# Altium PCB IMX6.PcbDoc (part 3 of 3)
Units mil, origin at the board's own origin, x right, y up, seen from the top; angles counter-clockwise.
Board outline 7950 x 5550 mil, 4 copper layers (Top Layer, GND, VCC, Bottom Layer), stack 30.634 mil thick; 238 components, 319 nets, 1015 pads, 404 vias.
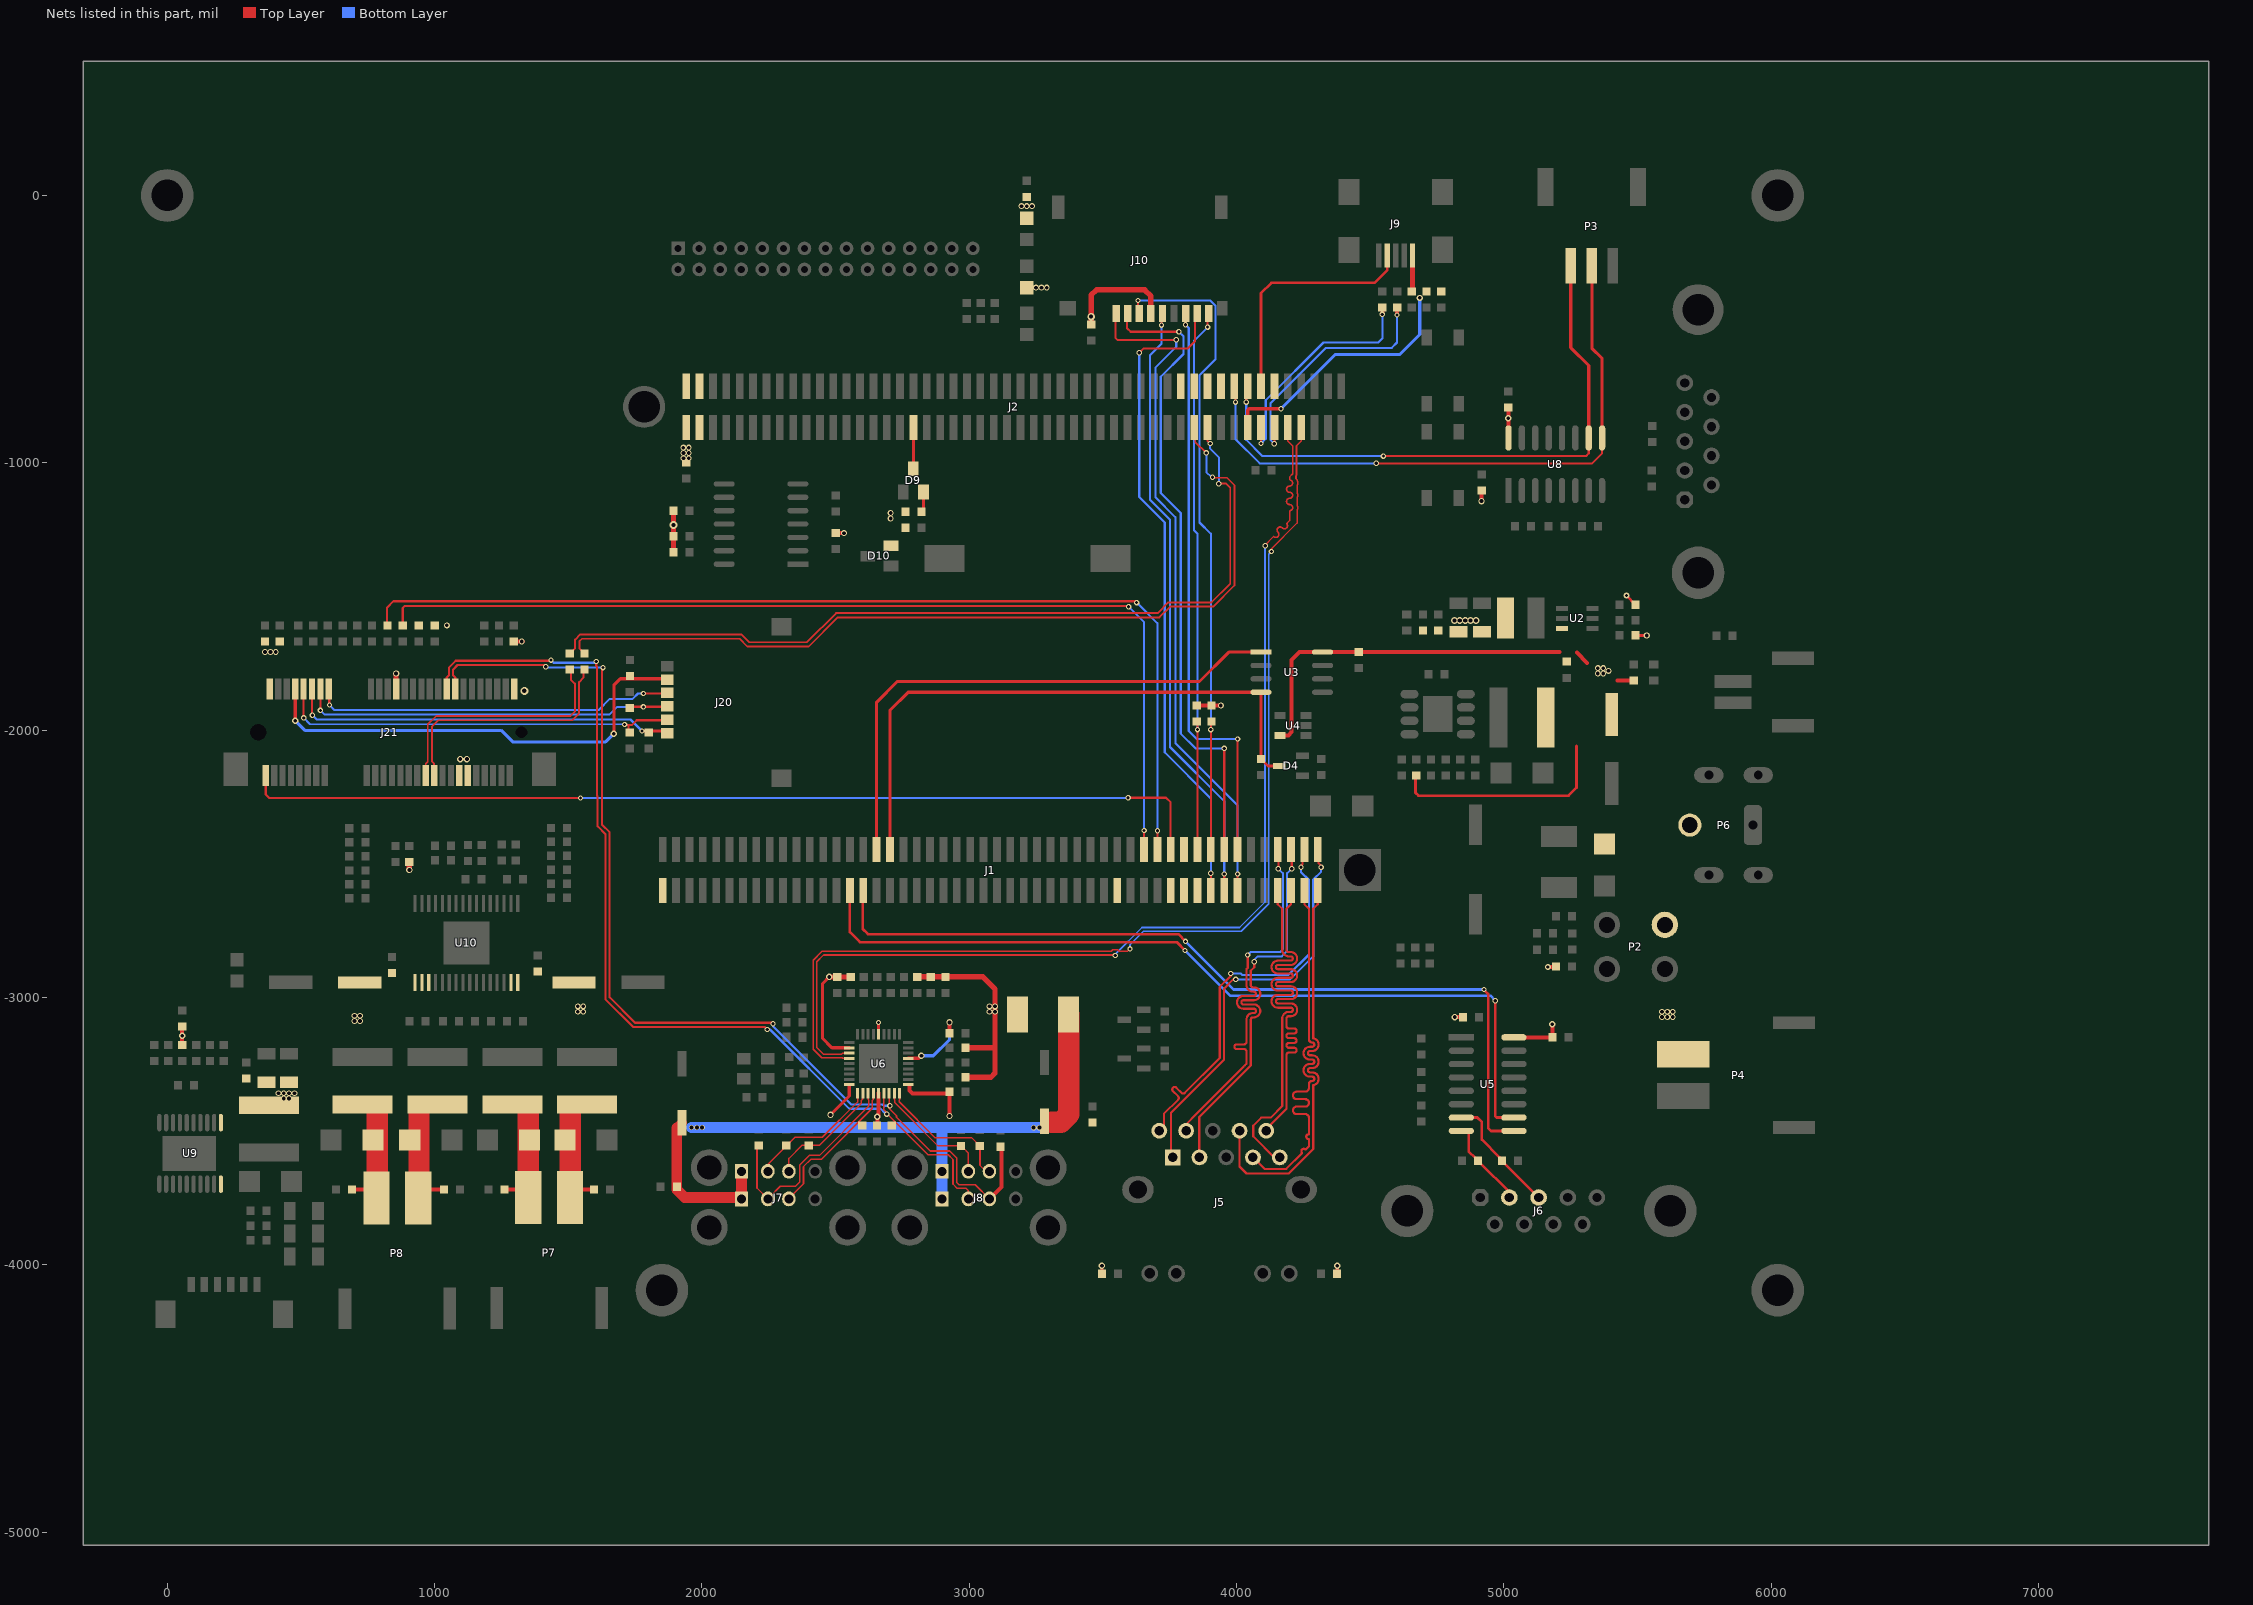
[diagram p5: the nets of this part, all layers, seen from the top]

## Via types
v1: diameter 20, hole 12, Top Layer to Bottom Layer, 138 vias
v2: diameter 22, hole 14, Top Layer to Bottom Layer, 54 vias
v3: diameter 24, hole 14, Top Layer to Bottom Layer, 53 vias
v4: diameter 22, hole 12, Top Layer to Bottom Layer, 39 vias
v5: diameter 23, hole 13, Top Layer to Bottom Layer, 38 vias
v6: diameter 22, hole 13, Top Layer to Bottom Layer, 21 vias
v7: diameter 30, hole 22, Top Layer to Bottom Layer, tented top, 15 vias
v8: diameter 22, hole 18, Top Layer to Bottom Layer, 6 vias
v9: diameter 25, hole 16, Top Layer to Bottom Layer, 5 vias
v10: diameter 24, hole 13, Top Layer to Bottom Layer, 5 vias
v11: diameter 20, hole 15, Top Layer to Bottom Layer, 5 vias
v12: diameter 30, hole 15, Top Layer to Bottom Layer, 4 vias
v13: diameter 18, hole 10, Top Layer to Bottom Layer, 4 vias
v14: diameter 20, hole 14, Top Layer to Bottom Layer, 4 vias
v15: diameter 28, hole 16, Top Layer to Bottom Layer, 3 vias
v16: diameter 26, hole 15, Top Layer to Bottom Layer, 3 vias
v17: diameter 45, hole 20, Top Layer to Bottom Layer, 1 vias
v18: diameter 28, hole 17, Top Layer to Bottom Layer, 1 vias
v19: diameter 25, hole 15, Top Layer to Bottom Layer, 1 vias
v20: diameter 28, hole 15, Top Layer to Bottom Layer, 1 vias
v21: diameter 18, hole 12, Top Layer to Bottom Layer, 1 vias
v22: diameter 30, hole 16, Top Layer to Bottom Layer, 1 vias
v23: diameter 25, hole 14, Top Layer to Bottom Layer, 1 vias

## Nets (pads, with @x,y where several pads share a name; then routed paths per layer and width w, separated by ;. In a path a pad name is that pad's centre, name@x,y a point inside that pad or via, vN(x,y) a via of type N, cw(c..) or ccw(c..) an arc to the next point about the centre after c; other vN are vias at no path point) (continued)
PCIE_TX_N: C118.1 J2.79 | length 3256.5
  Top Layer w7: C118.1@1506,-1713 1525.5,-1693.5 1525.5,-1661.37 1544.87,-1642 2147.63,-1642 2176.63,-1671 2393,-1671 2502,-1562 3704.37,-1562 3744.37,-1522 3906,-1522 3976,-1452 3976,-1093 3961,-1078 v1(3933,-1078) ; J2.79@3891.31,-867.49 3891.31,-918.73 3900.58,-928 v1(3901,-928)
  Bottom Layer w7: v1(3901,-928) 3901,-946.89 3933.84,-979.73 v1@3933.84,-1077
PCIE_TX_P: C119.1 J2.77 | length 3300.3
  Top Layer w7: C119.1@1561,-1713 1541.5,-1693.5 1541.5,-1668 1551.5,-1658 2141,-1658 2170,-1687 2399.63,-1687 2508.63,-1578 3711,-1578 3751,-1538 3912.63,-1538 3992,-1458.63 3992,-1084 3964,-1056 v1@3904,-1056 ; J2.77@3841.31,-867.49 3845.31,-871.49 3845.31,-922.31 v1(3886,-963)
  Bottom Layer w7: v1(3886,-963) 3887,-964 3887,-1035.31 v1@3904.69,-1053
  other v1: 3910,-1054
PCIE_TXO_N: C118.2 J21.31 | length 922.6
  Top Layer w7: J21.31@966.98,-2169.42 966.98,-2126.05 974.73,-2118.3 974.73,-1978.64 1006.37,-1947 1508.37,-1947 1524.69,-1930.69 1524.69,-1825.69 1510,-1811 C118.2@1510,-1778
PCIE_TXO_P: C119.2 J21.33 | length 919.2
  Top Layer w7: J21.33@998.48,-2169.42 998.48,-2126.05 990.73,-2118.3 990.73,-1985.27 1013,-1963 1515,-1963 1540.69,-1937.31 1540.69,-1820.31 1557,-1804 C119.2@1557,-1782
POR_B: D9.3 J2.35 | length 157.5
  Top Layer w12: J2.35@2791.31,-867.49 2791.31,-1018.31 D9.3@2796,-1023
PWM1_OUT: J1.1
RESET_B: D9.2 R93.1 | length 75.3
  Top Layer w12: R93.1@2826,-1183 2828.94,-1180.06 D9.2@2828.94,-1108.95
SATA_RX_N: J2.82
SATA_RX_P: J2.80
SATA_TX_N: J2.76
SATA_TX_P: J2.78
SD2_CD: J1.82 J10.9 R36.1 | length 2061.9
  Top Layer w8: J1.82@3853.52,-2446.23 v1(3853.52,-1998) R36.1@3853.52,-1970.52 ; v1(3891.5,-492.5) J10.9@3891.5,-437.89
  Bottom Layer w8: v1(3853.52,-1998) 3853.52,-1265.52 3841,-1253 3841,-543 v1(3891.5,-492.5)
SD2_CLK: J1.85 J10.5 | length 2295.4
  Top Layer w8: v1(3719,-485) J10.5@3719,-437.17 ; J1.85@3953.52,-2599.77 v1(3953.52,-2538)
  Bottom Layer w8: v1(3719,-485) 3719,-525 3719,-555 3676,-598 3676,-1138 3751,-1213 3751,-2063 3953.52,-2265.52 v1(3953.52,-2538)
SD2_CMD: J1.84 J10.3 R35.1 | length 2447
  Top Layer w8: J10.3@3629,-432.72 3631,-430.72 v1(3631,-393) ; J1.84@3903.52,-2446.23 v1(3903.52,-1998) R35.1@3903.52,-1965.52
  Bottom Layer w8: v1(3631,-393) 3901,-393 3921,-413 3921,-613 3861,-673 3861,-1223 3903.52,-1265.52 v1(3903.52,-1998)
SD2_DATA0: J1.88 J10.7 | length 2180.7
  Top Layer w8: J10.7@3806.14,-436.64 3809,-439.5 v1(3809,-484) ; J1.88@4003.52,-2446.23 v1(4003.52,-2033)
  Bottom Layer w8: v1(3809,-484) 3821,-496 3821,-2003 3851,-2033 v1(4003.52,-2033)
SD2_DATA1: J1.83 J10.8 | length 2438.4
  Top Layer w8: v1(3636,-588) 3651,-573 3816,-573 3844,-545 J10.8@3844,-455 ; J1.83@3903.52,-2599.77 v1(3903.52,-2535.52)
  Bottom Layer w8: v1(3636,-588) 3636,-1128 3731,-1223 3731,-2083 3903.52,-2255.52 v1(3903.52,-2535.52)
SD2_DATA2: J1.87 J10.1 | length 2546
  Top Layer w8: J10.1@3546.3,-436.64 3546.3,-532.3 3554,-540 v1(3774,-540) ; J1.87@4003.52,-2599.77 v1(4003.52,-2538)
  Bottom Layer w8: v1(3774,-540) 3774,-565.87 3696,-643.87 3696,-1128 3771,-1203 3771,-2048 4003.52,-2280.52 v1(4003.52,-2538)
SD2_DATA3: J1.86 J10.2 | length 2399.2
  Top Layer w8: J10.2@3589.61,-436.64 3589.61,-495.61 3604,-510 v1(3784,-510) ; J1.86@3953.52,-2446.23 v1(3953.52,-2068)
  Bottom Layer w8: v1(3784,-510) 3801,-527 3801,-593 3716,-678 3716,-1113 3791,-1188 3791,-2013 3846,-2068 v1(3953.52,-2068)
SD3_CMD: J1.77
SD3_DATA0: J1.80
SD3_DATA1: J1.74 R105.1 | length 3692.2
  Top Layer w8: R105.1@881,-1608 881,-1543 889,-1535 3593,-1535 v1@3600,-1542 ; J1.74@3654,-2415 v1@3654,-2374
  Bottom Layer w8: v1(3596,-1538) 3654,-1596 v1(3654,-2375)
SD3_DATA2: J1.76 R104.1 | length 3799.4
  Top Layer w8: R104.1@822,-1608 822,-1542 846,-1518 v1@3621,-1518 ; J1.76@3704,-2416 v1@3704,-2375
  Bottom Layer w8: v1@3627.5,-1523.5 3703.5,-1599.5 v1@3703.5,-2375.5
  other v1: 3704,-2376 3626,-1523
SD3_DATA4: J1.79
SD3_DATA5: J1.78 J21.1 | length 3616.8
  Top Layer w8: J21.1@368.56,-2182 368.56,-2240.56 381.56,-2253.56 v1(1546,-2253.56) ; J21.1@368.94,-2169.42 J21.1@369,-2163 ; v1(3594,-2253) 3736,-2253 3753,-2270 J1.78@3753,-2424
  Bottom Layer w8: v1(1546,-2253.56) v1@3595,-2253.56
SD3_DATA6: J1.81
SD3_DATA7: J1.69
SPEAK1+: C76.2 D14.K L9.2 P8.1 | length 402
  Top Layer w15: P8.1@974,-3718 C76.2@1036,-3718
  Top Layer w80: P8.1@941.91,-3748 L9.2@941.91,-3408
SPEAK1-: C80.1 D15.K L10.2 P8.2 | length 381
  Top Layer w15: C80.1@691,-3718 P8.2@762,-3718
  Top Layer w80: P8.2@786,-3718 L10.2@786,-3408
SPEAK2+: C70.2 D12.K L7.2 P7.1 | length 372
  Top Layer w15: P7.1@1534,-3718 C70.2@1596,-3718
  Top Layer w80: P7.1@1506.91,-3718 L7.2@1506.91,-3408
SPEAK2-: C72.1 D13.K L8.2 P7.2 | length 368
  Top Layer w15: C72.1@1261,-3718 P7.2@1324,-3718
  Top Layer w80: P7.2@1351,-3718 L8.2@1351,-3413
TRX0_N: J1.100 J5.2 | length 1505.7
  Top Layer w8: J5.2@3754,-3591 3754,-3431.63 3953,-3232.63 3953,-2966.81 3987.81,-2932 v1(3997,-2932) ; J1.100@4306.82,-2446.23 4306.82,-2497.52 4316,-2506.7 v1(4316,-2513)
  Bottom Layer w8: v1(3997,-2932) 4200.13,-2932 4286.5,-2845.63 4286.5,-2558.5 4316,-2529 v1(4316,-2513)
TRX0_P: J1.98 J5.1 | length 1456.8
  Top Layer w8: J5.1@3728,-3498 3728,-3435 3781,-3382 ccw(c3774.64,-3375.64) 3781,-3369.27 3761.82,-3350.09 cw(c3768.18,-3343.73) 3761.82,-3337.36 cw(c3768.18,-3343.73) 3774.55,-3337.36 3793.73,-3356.54 ccw(c3800.09,-3350.18) 3806.46,-3356.54 3937,-3226 3937,-2960.19 3978,-2919.19 v1(3978,-2910) ; v1(4241,-2513) 4241,-2507.68 4246.94,-2501.74 J1.98@4246.94,-2491.42
  Bottom Layer w8: v1(3978,-2910) 4015,-2910 4021,-2916 4193.5,-2916 4270.5,-2839 4270.5,-2560.5 4241,-2531 v1(4241,-2513) v1@4240.1,-2513.9
TRX1_N: J1.96 J5.4 | length 1506.9
  Top Layer w8: J5.4@3861,-3598 3860,-3597 3860,-3447 4053,-3254 4053,-3082 cw(c4061,-3082) 4061,-3074 4064.47,-3074 ccw(c4064.47,-3050) 4088.47,-3050 ccw(c4064.47,-3050) 4064.47,-3026 4025.53,-3026 cw(c4025.53,-3018) 4025.53,-3010 4064.47,-3010 ccw(c4064.47,-2986) 4088.47,-2986 ccw(c4064.47,-2986) 4064.47,-2962 4061,-2962 cw(c4061,-2954) 4053,-2954 4053,-2900 4066,-2887 v1(4066,-2866) ; J1.96@4203.52,-2446.23 4206,-2448.71 v1(4206,-2518)
  Bottom Layer w8: v1(4066,-2866) 4066,-2859 4079,-2846 4168.63,-2846 4189,-2825.63 4189,-2535 v1(4206,-2518)
TRX1_P: J1.94 J5.3 | length 1510
  Top Layer w8: J5.3@3811,-3498 3811,-3473.37 3848.69,-3435.69 4022.19,-3262.19 4030.64,-3253.74 4037,-3247.37 4037,-3202 ccw(c4028,-3202) 4028,-3193 4000.59,-3193 cw(c4000.59,-3184) 3991.59,-3184 cw(c4000.59,-3184) 4000.59,-3175 4028,-3175 ccw(c4028,-3166) 4037,-3166 4037,-3157 4037,-3148 4037,-3082 cw(c4061,-3082) 4061,-3058 4064.47,-3058 ccw(c4064.47,-3050) 4072.47,-3050 ccw(c4064.47,-3050) 4064.47,-3042 4025.53,-3042 cw(c4025.53,-3018) 4025.53,-2994 4064.47,-2994 ccw(c4064.47,-2986) 4072.47,-2986 ccw(c4064.47,-2986) 4064.47,-2978 4061,-2978 cw(c4061,-2954) 4037,-2954 4037,-2893.37 4041.69,-2888.69 4041.69,-2841.69 v1(4041,-2841) ; J1.94@4153.52,-2446.23 4156,-2448.71 v1(4156,-2518) v1@4154.05,-2518
  Bottom Layer w8: v1(4041,-2841) 4052,-2830 4162,-2830 4173,-2819 4173,-2535 v1(4156,-2518)
TRX2_N: J1.97 J5.8 | length 1572.1
  Top Layer w8: J5.8@4061,-3598 4104,-3641 4186,-3641 4244.66,-3582.34 ccw(c4243.95,-3581.64) 4244.66,-3580.93 cw(c4251.02,-3574.57) 4244.66,-3568.2 cw(c4251.02,-3574.57) 4257.38,-3568.2 ccw(c4258.09,-3567.49) 4258.8,-3568.2 4270.52,-3556.48 4270.52,-3530.48 ccw(c4269.52,-3530.48) 4269.52,-3529.48 cw(c4269.52,-3520.48) 4260.52,-3520.48 cw(c4269.52,-3520.48) 4269.52,-3511.48 ccw(c4269.52,-3510.48) 4270.52,-3510.48 4270.52,-3450 ccw(c4256.52,-3450) 4256.52,-3436 4224.52,-3436 cw(c4224.52,-3422) 4210.52,-3422 cw(c4224.52,-3422) 4224.52,-3408 4256.52,-3408 ccw(c4256.52,-3394) 4270.52,-3394 ccw(c4256.52,-3394) 4256.52,-3380 4224.52,-3380 cw(c4224.52,-3366) 4210.52,-3366 cw(c4224.52,-3366) 4224.52,-3352 4256.52,-3352 ccw(c4256.52,-3338) 4270.52,-3338 4270.52,-3324 cw(c4282.52,-3324) 4282.52,-3312 ccw(c4282.52,-3304) 4290.52,-3304 ccw(c4282.52,-3304) 4282.52,-3296 4274.52,-3296 cw(c4274.52,-3272) 4274.52,-3248 4282.52,-3248 ccw(c4282.52,-3240) 4290.52,-3240 ccw(c4282.52,-3240) 4282.52,-3232 4274.52,-3232 cw(c4274.52,-3208) 4274.52,-3184 4282.52,-3184 ccw(c4282.52,-3176) 4290.52,-3176 ccw(c4282.52,-3176) 4282.52,-3168 cw(c4282.52,-3156) 4270.52,-3156 4270.52,-2800.6 ; J1.97@4253.52,-2599.77 4253.52,-2651.02 4270.52,-2668.02 4270.52,-2804
TRX2_P: J1.99 J5.7 | length 1554.4
  Top Layer w8: J5.7@4011,-3504 4011,-3632 4037,-3658 4195,-3658 4286.52,-3566.48 4286.52,-3327.66 ccw(c4282.52,-3304) 4306.52,-3304 ccw(c4282.52,-3304) 4282.52,-3280 4274.52,-3280 cw(c4274.52,-3272) 4274.52,-3264 4282.52,-3264 ccw(c4282.52,-3240) 4306.52,-3240 ccw(c4282.52,-3240) 4282.52,-3216 4274.52,-3216 cw(c4274.52,-3208) 4274.52,-3200 4282.52,-3200 ccw(c4282.52,-3176) 4306.52,-3176 ccw(c4282.52,-3176) 4286.52,-3152.34 4286.52,-2800.6 ; 4286.52,-2804 4286.52,-2668.02 4303.52,-2651.02 J1.99@4303.52,-2599.77
TRX3_N: J1.93 J5.10 | length 1563.9
  Top Layer w8: J5.10@4147,-3600 4143,-3600 4062,-3519 4062,-3479 4092,-3449 4127,-3449 4170.52,-3405.48 4170.52,-3078 cw(c4194.52,-3078) 4194.52,-3054 4202.41,-3054 ccw(c4202.41,-3046) 4210.41,-3046 ccw(c4202.41,-3046) 4202.41,-3038 4154.63,-3038 cw(c4154.63,-3014) 4154.63,-2990 4202.41,-2990 ccw(c4202.41,-2982) 4210.41,-2982 ccw(c4202.41,-2982) 4202.41,-2974 4154.63,-2974 cw(c4154.63,-2950) 4154.63,-2926 4202.41,-2926 ccw(c4202.41,-2918) 4210.41,-2918 ccw(c4202.41,-2918) 4202.41,-2910 4154.63,-2910 cw(c4154.63,-2886) 4154.63,-2862 4202.41,-2862 ccw(c4202.41,-2854) 4210.41,-2854 ccw(c4202.41,-2854) 4202.41,-2846 4194.52,-2846 cw(c4194.52,-2822) 4170.52,-2822 4170.52,-2668.02 4153.52,-2651.02 J1.93@4153.52,-2599.77
  Bottom Layer w8: J5.10@4161,-3598 J5.10@4166,-3598
TRX3_P: J1.95 J5.9 | length 1564.3
  Top Layer w8: J5.9@4108,-3494 4186.52,-3415.48 4186.52,-3276 4186.52,-3215 cw(c4195.52,-3215) 4195.52,-3206 4215.32,-3206 ccw(c4215.32,-3197) 4224.32,-3197 ccw(c4215.32,-3197) 4215.32,-3188 4195.52,-3188 cw(c4195.52,-3179) 4186.52,-3179 cw(c4195.52,-3179) 4195.52,-3170 4215.32,-3170 ccw(c4215.32,-3161) 4224.32,-3161 ccw(c4215.32,-3161) 4215.32,-3152 4195.52,-3152 cw(c4195.52,-3143) 4186.52,-3143 cw(c4195.52,-3143) 4195.52,-3134 4215.32,-3134 ccw(c4215.32,-3125) 4224.32,-3125 ccw(c4215.32,-3125) 4215.32,-3116 4195.52,-3116 cw(c4195.52,-3107) 4186.52,-3107 4186.52,-3078 cw(c4194.52,-3078) 4194.52,-3070 4202.41,-3070 ccw(c4202.41,-3046) 4226.41,-3046 ccw(c4202.41,-3046) 4202.41,-3022 4154.63,-3022 cw(c4154.63,-3014) 4154.63,-3006 4202.41,-3006 ccw(c4202.41,-2982) 4226.41,-2982 ccw(c4202.41,-2982) 4202.41,-2958 4154.63,-2958 cw(c4154.63,-2950) 4154.63,-2942 4202.41,-2942 ccw(c4202.41,-2918) 4226.41,-2918 ccw(c4202.41,-2918) 4202.41,-2894 4154.63,-2894 cw(c4154.63,-2886) 4154.63,-2878 4202.41,-2878 ccw(c4202.41,-2854) 4226.41,-2854 ccw(c4202.41,-2854) 4202.41,-2830 4194.52,-2830 cw(c4194.52,-2822) 4186.52,-2822 4186.52,-2668.02 4203.52,-2651.02 J1.95@4203.52,-2599.77
  Bottom Layer w8: J5.9@4111,-3499.47 J5.9@4111,-3498
U2_RXD: D20.1 J6.2 U5.8 | length 290.2
  Top Layer w10: U5.8@4861,-3498 4868,-3505 4868,-3575 D20.1@4893,-3600 ; D20.1@4910.5,-3618.5 5020.17,-3728.17 J6.2@5020.17,-3748
U2_TXD: D21.1 J6.3 U5.7 | length 388.7
  Top Layer w10: U5.7@4875.24,-3448.91 4899.91,-3448.91 4917,-3466 4917,-3531 D21.1@4984,-3598 ; D21.1@5002,-3620.67 J6.3@5129.33,-3748
UART1_RX: J2.84 P3.2 U8.9 | length 2336.2
  Top Layer w8: J2.84@3991.31,-713.94 3996,-718.63 v1(3996,-773) ; v1(4522,-1002) 5329.61,-1002 5366.91,-964.7 U8.9@5366.91,-906.91
  Top Layer w12: P3.2@5328.74,-263 5328.74,-571.74 5366.91,-609.91 U8.9@5366.91,-906.91
  Bottom Layer w8: v1@3996,-778 3996,-912 4086,-1002 v1(4522,-1002)
UART1_TX: J2.86 P3.1 U8.10 | length 2237.1
  Top Layer w8: v1(4036,-773) 4036,-719.26 J2.86@4041.31,-713.94 ; v1(4549,-975) 5306.61,-975 5316.91,-964.7 U8.10@5316.91,-906.91
  Top Layer w12: P3.1@5250,-263 5250,-569 5316.91,-635.91 U8.10@5316.91,-906.91
  Bottom Layer w8: v1@4036,-778 4036,-914 4097,-975 v1(4549,-975)
UART2_RX: J1.31 U5.9 | length 3178.3
  Top Layer w10: J1.31@2601.52,-2599.77 2601.52,-2743.52 2621,-2763 3782,-2763 v1(3809,-2790) ; v1@4925,-2971 4941,-2987 4941,-3488 4951.91,-3498.91 U5.9@5037.09,-3498.91
  Bottom Layer w10: v1(3809,-2790) 3989,-2970 v1@4918,-2970
  other v1: 4925,-2970
UART2_TX: J1.29 U5.10 | length 3178.5
  Top Layer w10: J1.29@2553.52,-2599.48 2553.52,-2755.52 2591,-2793 3776,-2793 v1(3807,-2824) ; v1@4966.91,-3013 4966.91,-3443.91 4971.91,-3448.91 U5.10@5037.09,-3448.91
  Bottom Layer w10: v1(3807,-2824) 3976,-2993 4949,-2993 v1@4967,-3011
  other v1: 4967,-3012
UART3_RX: J1.34 U3.1 | length 2055.9
  Top Layer w12: J1.34@2653.52,-2446.23 2653.52,-1895.48 2731,-1818 3861,-1818 3971,-1708 U3.1@4081,-1708
UART3_TX: D4.3 J1.36 R18.2 U3.4 | length 2265.9
  Top Layer w10: U3.4@4091,-1858 R18.2@4091,-2108 4117.06,-2134.06 D4.3@4159.95,-2134.06
  Top Layer w12: J1.36@2703.52,-2446.23 2703.52,-1925.48 2771,-1858 U3.4@4091,-1858
UIM_CLK: D31.1 J20.6 J21.12 | length 1469
  Top Layer w8: v1@542,-1946 J21.12@542,-1831.36 ; J20.6@1865.44,-2003 J20.6@1870.44,-2008
  Top Layer w10: v1(1776,-2003) J20.6@1865.44,-2003
  Bottom Layer w8: v1@543,-1943 560,-1960 1733,-1960 v1(1776,-2003)
  other v1: 543,-1944
UIM_DATA: D30.2 J20.5 J21.10 | length 1496.7
  Top Layer w8: v1@510,-1957 J21.10@510,-1861.36 ; J21.10@510.02,-1846.58 J21.10@510,-1843 ; v1@1711.17,-1980.17 1738.83,-1980.17 1756,-1963 J20.5@1864,-1963 ; D30.2@1725.09,-2007.91 1725.09,-1981.08
  Bottom Layer w8: v1(511,-1954) 534.25,-1977.29 v1@1712,-1978.37
  other v1: 1711,-1979
UIM_PWR: C1.1 J20.2 J21.8 | length 1753.1
  Top Layer w8: J21.8@477,-1840 J21.8@477.23,-1846.64
  Top Layer w12: v10@479,-1966 J21.8@479,-1842 ; v10@1671,-2005 1671,-1832 1695,-1808 J20.2@1870.44,-1808
  Bottom Layer w12: v10(479,-1965) 515,-2001 1249,-2001 1292,-2044 1639.72,-2044 v10@1672.72,-2011
  other v10: 1671,-2013
UIM_RESET: D32.1 J20.4 J21.14 | length 1470.2
  Top Layer w8: v1@573,-1928 J21.14@573,-1824.36
  Top Layer w10: D32.1@1730.09,-1913 J20.4@1874,-1913
  Bottom Layer w8: v1(573,-1926) 589,-1942 1654,-1942 1683,-1913 v1@1777,-1913
  other v1: 1781,-1913
UIM_VPP: J20.3 J21.16 | length 1356.8
  Top Layer w8: v1@606,-1906 J21.16@606,-1825.36 ; v1(1781,-1863) J20.3@1860,-1863
  Bottom Layer w8: v1@608,-1907 626,-1925 1613,-1925 1655,-1883 1741,-1883 1761,-1863 v1@1772,-1863
  other v1: 607,-1906
USB_H1_D_N: J2.91 U6.30 | length 4163.3
  Top Layer w6: U6.30@2550.76,-3207.72 2527.08,-3207.72 2523.24,-3211.57 2454.37,-3211.57 2430,-3187.2 2430,-2866.17 2455.17,-2841 3536.69,-2841 3540.34,-2837.34 v1(3546,-2843) ; v1(4107,-1310) 4107,-1309 4106,-1308 4138.21,-1275.79 ccw(c4146.34,-1267.66) 4154.47,-1259.53 cw(c4162.6,-1251.4) 4170.74,-1243.26 ccw(c4178.87,-1235.13) 4187,-1227 4198,-1216 4198,-1179 ccw(c4198,-1167.5) 4198,-1156 cw(c4198,-1144.5) 4198,-1133 ccw(c4198,-1121.5) 4198,-1110 cw(c4198,-1098.5) 4198,-1087 ccw(c4198,-1075.5) 4198,-1064 4198,-1053 4210,-1041 4210,-937.42 4191.31,-918.73 J2.91@4191.31,-867.49
  Bottom Layer w6: v1(3546,-2843) 3546,-2838 3646,-2738 4011,-2738 4106,-2643 v1@4106,-1308
USB_H1_D_P: J2.93 U6.31 | length 4127.2
  Top Layer w6: U6.31@2550.76,-3227.41 2527.08,-3227.41 2525.24,-3225.57 2448.57,-3225.57 2416,-3193 2416,-2860.37 2449.37,-2827 3530.89,-2827 3536.89,-2821 3555.11,-2821 3561.11,-2827 3592,-2827 v1(3601,-2818) ; v1(4130,-1332) 4130,-1321 4226,-1225 4226,-1179.19 4226.31,-1178.88 4226.31,-1178.35 4226.86,-1177.8 4226.86,-1175.97 4227.29,-1175.54 4227.29,-1174.83 4227.41,-1174.7 4227.41,-1173.56 4227.85,-1173.13 4227.85,-1170.21 4228.08,-1169.98 4228.08,-1165.02 4227.85,-1164.79 4227.85,-1161.87 4227.41,-1161.44 4227.41,-1160.3 4227.29,-1160.17 4227.29,-1159.46 4226.86,-1159.03 4226.86,-1157.2 4226.31,-1156.65 4226.31,-1156.12 4226,-1155.81 4226,-1133.19 4226.31,-1132.88 4226.31,-1132.35 4226.86,-1131.8 4226.86,-1129.97 4227.29,-1129.54 4227.29,-1128.83 4227.41,-1128.7 4227.41,-1127.56 4227.85,-1127.13 4227.85,-1124.21 4228.08,-1123.98 4228.08,-1119.02 4227.85,-1118.79 4227.85,-1115.87 4227.41,-1115.44 4227.41,-1114.3 4227.29,-1114.17 4227.29,-1113.46 4226.86,-1113.03 4226.86,-1111.2 4226.31,-1110.65 4226.31,-1110.12 4226,-1109.81 4226,-1087.19 4226.31,-1086.88 4226.31,-1086.35 4226.86,-1085.8 4226.86,-1083.97 4227.29,-1083.54 4227.29,-1082.83 4227.41,-1082.7 4227.41,-1081.56 4227.85,-1081.13 4227.85,-1078.21 4228.08,-1077.98 4228.08,-1073.02 4227.85,-1072.79 4227.85,-1069.87 4227.41,-1069.44 4227.41,-1068.3 4227.29,-1068.17 4227.29,-1067.46 4226.86,-1067.03 4226.86,-1065.2 4226.31,-1064.65 4226.31,-1064.12 4222,-1059.81 4222,-1048.8 4224,-1046.8 4224,-936.05 4241.31,-918.73 J2.93@4241.31,-867.49
  Bottom Layer w6: v1(3601,-2818) 3601,-2802.8 3651.8,-2752 4016.8,-2752 4120,-2648.8 4120,-1342 v1(4130,-1332)
USB_H1_OC: J2.90
USB_OTG_D_N: J2.89 R33.2 | length 905.7
  Top Layer w8: v1(4141,-928.51) J2.89@4141,-878
  Top Layer w15: v1(4600,-447) R33.2@4600,-420
  Bottom Layer w8: v1(4141,-928.51) 4126,-913.51 4126,-778 4334,-570 4580,-570 4600,-550 v1(4600,-447)
USB_OTG_D_P: J2.87 R34.2 | length 866.7
  Top Layer w8: v1@4091,-928.51 J2.87@4091,-878
  Top Layer w15: v1(4545,-445) R34.2@4545,-420
  Bottom Layer w8: v1(4091,-928) 4109,-910 4109,-766 4325,-550 4530,-550 4545,-535 v1(4545,-445)
USB_OTG_ID: J2.88 J9.4 | length 910.6
  Top Layer w10: J2.88@4091.31,-713.94 4091.31,-365.69 4130,-327 4516,-327 4563.5,-279.5 J9.4@4563.5,-225
USB_OTG_VBUS: C47.2 C48.2 C49.2 J2.85 J9.1 | length 1094.6
  Top Layer w12: J2.85@4041.31,-867.49 4041.31,-802.69 4046,-798 v1(4166,-798)
  Top Layer w18: C48.2@4658,-354.01 J9.1@4658,-222
  Bottom Layer w12: v1(4166,-798) 4369,-595 4610,-595 4685,-520 v5(4685,-383)
USB_PORT1_N: D22.1 J7.2 U6.1 | length 491.4
  Top Layer w6: J7.2@2246.63,-3649.97 2246.63,-3624.37 2348,-3523 2450,-3523 2582.26,-3390.74 U6.1@2582.26,-3357.33
USB_PORT1_P: D24.1 J7.3 U6.2 | length 446
  Top Layer w6: J7.3@2325.37,-3649.97 2325.37,-3601.63 2374,-3553 2439.8,-3553 2596.26,-3396.54 2596.26,-3384.74 2601.95,-3379.06 U6.2@2601.95,-3357.33 U6.2@2601.77,-3357.5
USB_PORT2_N: D23.2 J7.6 U6.3 | length 815.5
  Top Layer w6: D23.2@2211.91,-3553.09 2206,-3559 2206,-3712.49 J7.6@2246.63,-3753.12 ; J7.6@2254.5,-3744.5 2293,-3706 2350,-3706 2366,-3690 2366,-3626.37 2401.96,-3590.41 2439.59,-3590.41 2623.47,-3406.53 2623.47,-3382.86 2621.63,-3381.02 U6.3@2621.63,-3357.33
USB_PORT2_P: D25.2 J7.7 U6.4 | length 566.5
  Top Layer w6: J7.7@2313.81,-3764.81 2313.81,-3762.19 2375,-3701 2375,-3700.8 2380,-3695.8 2380,-3632.17 2407.76,-3604.41 2447.59,-3604.41 2637.47,-3414.53 2637.47,-3384.86 2641.32,-3381.02 U6.4@2641.32,-3357.33
USB_PORT3_N: D27.2 J8.6 J21.36 U6.6 | length 3774.5
  Top Layer w6: U6.6@2680.68,-3357.33 2680.68,-3419.68 2691,-3430 v1(2691,-3436) v1@2697,-3436 ; v1@2693.5,-3435.5 2846,-3588 2921,-3588 2939,-3606 2939,-3697.63 2955.37,-3714 2989,-3714 2996.63,-3721.63 J8.6@2996.63,-3753.12
  Top Layer w8: J21.36@1045.73,-1846.58 1045.73,-1803.21 1053.47,-1795.46 1053.47,-1766.37 1079.36,-1740.49 v1@1435.49,-1740.49 ; v1@1435.49,-1743 v1(1435.49,-1738) ; v1(1605,-1743) 1605,-1759.37 1608,-1762.37 1608,-2246 1610,-2248 1610,-2359.63 1638.81,-2388.44 1638.81,-3005.81 1743.19,-3110.19 2235.56,-3110.19 v1(2244.69,-3119.31) ; D27.2@2700.09,-3477.91 D27.2@2708,-3470.01
  Bottom Layer w8: v1(1435.49,-1738) 1445.49,-1748 v1@1604,-1748 ; v1(2244.69,-3119.31) 2254.69,-3119.31 2551.37,-3416 2668.37,-3416 2684.37,-3432 v1@2694,-3432 ; v1(2691,-3436) 2692,-3436 v1@2695,-3433
USB_PORT3_P: D29.2 J8.7 J21.38 U6.7 | length 3947.7
  Top Layer w6: U6.7@2700.37,-3357.33 2700.37,-3415.09 2718.24,-3433 2727.68,-3442.44 2727.68,-3447.68 2854,-3574 2926.8,-3574 2953,-3600.2 2953,-3691.83 2961.17,-3700 3022.25,-3700 J8.7@3075.37,-3753.12
  Top Layer w8: J21.38@1077.22,-1846.58 1077.22,-1803.21 1069.47,-1795.46 1069.47,-1773 1085.98,-1756.49 1411.49,-1756.49 1416,-1761 v1(1416,-1763) ; v1(1630,-1766) 1626,-1770 1626,-2353 1654.81,-2381.81 1654.81,-2999.19 1749.81,-3094.19 2263.19,-3094.19 v1@2266.5,-3097.5 ; v1(2266,-3098) v1@2267,-3098 ; J8.7@3075.37,-3753.12 J8.7@3075.88,-3753.12
  Top Layer w15: J8.7@3075.88,-3753.12 3121,-3708 D29.2@3121,-3568
  Bottom Layer w8: v1@1422,-1766 v1(1630,-1766) ; v1(2266,-3098) 2266,-3108 2558,-3400 2675,-3400 2682,-3407 2684,-3405 v1(2703,-3405)
USB_PORT4_N: D26.1 J8.2 U6.8 | length 441.9
  Top Layer w6: U6.8@2720.05,-3357.33 2720.05,-3381.02 2721.9,-3382.86 2721.9,-3393.63 2883.27,-3555 D26.1@2968,-3555 ; D26.1@2980,-3565 2996.63,-3581.63 J8.2@2996.63,-3649.97
USB_PORT4_P: D28.1 J8.3 U6.9 | length 515.3
  Top Layer w6: U6.9@2739.74,-3357.33 2739.74,-3381.02 2737.9,-3382.86 2737.9,-3389.83 2873.07,-3525 3010,-3525 3040,-3555 3040,-3628 3063,-3651 J8.3@3069,-3651
VBUS: C29.1 C30.2 C36.1 C37.2 F2.2 J7.1 J7.5 J8.1 J8.5 | length 2626.3
  Top Layer w35: 1906,-3488 C36.1@1926,-3468
  Top Layer w40: 1906,-3488 1906,-3718 1936,-3748 2143.09,-3748 J7.5@2148.2,-3753.12 J7.1@2148.2,-3649.97
  Top Layer w80: 3308,-3466 3343,-3466 3371.94,-3437.06 F2.2@3371.94,-3063
  Bottom Layer w30: J8.5@2898,-3756 J8.5@2898.02,-3753.12
  Bottom Layer w40: v11(1961,-3486) v11(1981,-3486) v11(2001,-3486) v11@3261,-3486 ; J8.5@2898.2,-3747 2898.2,-3491.8
  other v11: 3241,-3487 3262,-3487
VCC3V3: C7.2 C25.2 C32.2 C34.2 C35.2 C40.2 C41.2 C42.2 C43.2 C44.2 C50.2 C86.1 C87.1 C88.1 C109.1 C110.1 C111.1 D10.2 J10.4 J21.2 J21.24 J21.39 J21.41 J21.52 L5.2 L11.1 R9.2 R10.2 R11.2 R19.2 R24.1 R35.2 R36.2 R44.2 R57.1 R58.1 R89.1 R90.1 R93.2 R112.2 R113.2 R114.2 R115.2 U5.16 U6.5 U6.10 U6.15 U6.23 U6.29 U6.36 U8.16 | length 2654.1
  Top Layer w12: v3(2476,-2923) 2451,-2948 2451,-3153 2486.04,-3188.04 U6.29@2550.76,-3188.04 ; v3(2481,-3439) 2481,-3438 2550.76,-3368.24 U6.36@2550.76,-3325.83 ; U6.23@2661,-3136.86 v21(2661,-3093) ; U6.15@2771.24,-3227.41 2811.59,-3227.41 v3(2821,-3218) ; R10.2@3496,-4033 v3(3496,-4003) ; R11.2@4376,-4033 v3(4376,-4003) ; R58.1@5490,-1646 v3(5534,-1646)
  Top Layer w15: R44.2@56,-3178 C32.2@56,-3108 ; C43.2@1296,-1668 v2@1331,-1668 ; R112.2@2501,-1263 v2(2531,-1263) ; C41.2@2651,-3478 2656,-3473 v3(2656,-3446) 2661,-3441 U6.5@2661,-3357.33 ; 2776,-3333 2776,-3348 2787.38,-3359.38 2919.62,-3359.38 C42.2@2926,-3353 v3(2926,-3443) ; C109.1@2926,-3133 v3(2926,-3093) ; R36.2@3856,-1908 v2(3941,-1908) ; v3(4816,-3073) C25.2@4846,-3073 ; v3(4916,-1143) C7.2@4916,-1103 ; U8.16@5016.91,-906.91 C35.2@5016.91,-793.91 ; U5.16@5037.09,-3148.91 C34.2@5180.09,-3148.91 ; v3(5180,-3100) 5181,-3101 C34.2@5181,-3148
  Top Layer w20: v3(856,-1788) 856,-1845.83 J21.24@856.75,-1846.58 ; v3(906,-2523) R57.1@906,-2493 ; R113.2@1894,-1333 R115.2@1894,-1179 ; v3(2476,-2923) R19.2@2506,-2923 R24.1@2556,-2923 ; C110.1@3456,-483 3456,-373 3476,-353 3656,-353 3679.22,-376.22 J10.4@3679.22,-441.64
  Bottom Layer w12: v3(2821,-3218) 2866.04,-3218 2926,-3158.04 v3(2926,-3093)
  other v2: 366,-1708 386,-1708 406,-1708 1326,-1668 1046,-1608 2706,-1208 2706,-1188 3195,-40 3215,-40 3235,-40
  other v3: 56,-3143 1096,-2108 1121,-2108 5016,-833
  other v9: 4815,-1590 4835,-1590 4855,-1590 4875,-1590 4895,-1590
  other v12: 1894,-1233
  other v20: 3456,-453
  other v22: 1336,-1853
VCC5V: C2.1 C5.1 C17.1 C18.1 C23.1 F2.1 J2.1 J2.2 J2.3 J2.4 L1.2 L4.1 R2.2 R3.1 R4.1 R17.1 R20.1 R21.1 R22.1 R23.1 U2.3 U3.8 U4.5 | length 3191.8
  Top Layer w10: R2.2@4669,-2170 4669,-2234 4680,-2245 5241,-2245 5271,-2215 5271,-2059 ; v4@5457.5,-1496.5 R4.1@5492,-1531
  Top Layer w15: 3095.96,-3188.04 3096,-3188 ; U4.5@4162.77,-2020.4 4193.28,-2020.4 4206,-2007.69 4206,-1738 4236,-1708 U3.8@4321.31,-1708 5207,-1708 ; v4(5164,-2886) R17.1@5188,-2886 ; 5273,-1710 5311,-1748 ; 5425,-1815 R3.1@5485,-1815
  Top Layer w20: R23.1@2806.04,-2922.68 3050.68,-2922.68 3096,-2968 3096,-3188 3096,-3283 3080.96,-3298.04 R20.1@2986,-3298 ; 3001.32,-3188.04 3095.96,-3188.04
  other v2: 3076,-3053 3096,-3053 3076,-3033 3096,-3033 5351,-1788 5371,-1788 5391,-1778 5351,-1768 5371,-1768 1931,-983 1951,-983 1931,-963 1951,-963 3250,-345 3270,-345 3290,-345
  other v4: 5458,-1496
  other v6: 1931,-943 1951,-943
VIN: C57.1 C58.2 C59.2 C65.1 C66.1 C83.1 C84.1 D2.A L6.1 P2.4 P4.1 P6.2 U9.1 U9.20 U10.17 U10.18 U10.19 U10.31 U10.32
  other v2: 436,-3378 456,-3378 416,-3358 436,-3358 456,-3358 476,-3358 701,-3088 721,-3088 5591,-3073 5611,-3073 5631,-3073 701,-3068 721,-3068 1536,-3053 1556,-3053 5591,-3053 5611,-3053 5631,-3053 1536,-3033 1556,-3033
pads on no net: D4.2 D9.1 J3.1 J3.4 J3.6 J3.7 J3.8 J3.9 J6.1 J6.4 J6.6 J6.7 J6.8 J6.9 J20. J21.3 J21.5 J21.7 J21.17 J21.19 J21.42 J21.44 J21.45 J21.46 J21.47 J21.49 J21.51 J21.53 J21.54 J21.55 J21.56 U1.3 U4.1 U5.11 U5.12 U5.13 U5.14 U6.12 U6.16 U6.18 U6.20 U8.11 U8.12 U8.13 U8.14 U9.5 U9.8 U9.19 U10.16 U25.1 U25.3 U25.4 U25.7 U25.8 U25.9 U25.14
copper on no net: | length 761.4
  Top Layer w30: 1520,-1235 1570,-1285 ; 1570,-665 1570,-1285 ; 1620,-1235 1570,-1285

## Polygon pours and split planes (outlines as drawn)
EARTH on Top Layer "EARTH_L01_P082" (solid, remove dead copper, pour order 82): 5560,140 6220,140 6200,120 6200,-340 5580,-340 5560,-320
EARTH on Top Layer "EARTH_L01_P080" (solid, remove dead copper, pour order 80): 3280,160 3280,-180 4880,-180 4900,-160 4900,-80 5600,-80 5620,-60 5620,160
EARTH on Top Layer "EARTH_L01_P040" (solid, remove dead copper, pour order 40): 5531,-3658 6171,-3658 6171,-4198 6111,-4258 5491,-4258 5491,-3658
EARTH on Top Layer "EARTH_L01_P026" (solid, remove dead copper, pour order 26): 2471,-3618 2471,-4258 2891,-4258 3271,-4258 3271,-3998 2871,-3998 2871,-3818 2851,-3778 2851,-3758 2851,-3618
EARTH on Top Layer "EARTH_L01_P022" (solid, remove dead copper, pour order 22): 3231,-3578 3231,-4258 3451,-4258 3451,-3578
EARTH on Top Layer "EARTH_L01_P016" (solid, remove dead copper, pour order 16): 5491,-3958 5491,-4258 4491,-4258 4491,-3938 4491,-3678 4811,-3678 4811,-3958 4831,-3978 5531,-3978
EARTH on Top Layer "EARTH_L01_P010" (solid, remove dead copper, pour order 10): 6031,-1498 6031,-3658 6051,-3678 6171,-3678 6171,-1498 6151,-1478
EARTH on Top Layer "EARTH_L01_P006" (solid, remove dead copper, pour order 6): 5611,-298 6171,-298 6171,-1518 5649.33,-1518 5609.33,-1478 5611,-1476.33 5611,-1258 5871,-1258 5891,-1238 5891,-618 5651,-618 5611,-578 5611,-298
VIN on Top Layer "Top Layer-No Net 1" (solid, remove dead copper, pour order 0): 5681,-2658 5941,-2658 5941,-3268 5941,-3288 5551,-3288 5551,-2998 5577,-2978 5733,-2978 5733,-2797.47 5759,-2777.47
VIN on Top Layer "Top Layer-No Net 1" (solid, remove dead copper, pour order 2): 5481,-2298 5481,-2818 5711,-2818 5711,-2598 5691,-2578 5681,-2578 5681,-2478 5731,-2428 5751,-2408 5751,-2298
GND on Top Layer "GND_L01_P084" (solid, remove dead copper, pour order 84): 4500,-1375 6250,-1375 6250,-4250 6175,-4325 6125,-4375 4500,-4375
EARTH on Bottom Layer "EARTH_L04_P076" (solid, remove dead copper, pour order 76): 5480,-3660 6220,-3660 6220,-4260 6180,-4300 5480,-4300
EARTH on Bottom Layer "EARTH_L04_P074" (solid, remove dead copper, pour order 74): 3440,-3680 4780,-3680 4800,-3700 4800,-4320 3420,-4320
EARTH on Bottom Layer "EARTH_L04_P072" (solid, remove dead copper, pour order 72): 3200,-3540 3460,-3540 3460,-4260 3440,-4280 2780,-4280 2780,-3820 3200,-3820
EARTH on Bottom Layer "EARTH_L04_P070" (solid, remove dead copper, pour order 70): 2080,-3800 2460,-3800 2460,-3580 2480,-3560 2840,-3560 2860,-3580 2860,-4320 2060,-4320 2040,-4300
EARTH on Bottom Layer "EARTH_L04_P066" (solid, remove dead copper, pour order 66): 1700,-3560 2100,-3560 2100,-4260 1700,-4260
EARTH on Bottom Layer "EARTH_L04_P088" (solid, remove dead copper, pour order 88): 5500,250 5525,275 6250,275 6250,-1475 6200,-1525 5500,-1525
AUGND on GND (split plane): 1826.92,-2398.96 1826.92,-3619.24 1677.24,-3768.92 259.76,-3768.92 225.08,-3734.24 225.08,-2906.76 239.76,-2892.08 576,-2892.08 578.35,-2891.77 580.54,-2890.86 582.42,-2889.42 622.42,-2849.42 623.86,-2847.54 624.77,-2845.35 625.08,-2843 625.08,-2376.76 664.76,-2337.08 1765.04,-2337.08
GND on GND (split plane): 7615.9,-5027.9 -293.9,-5027.9 -293.9,481.9 7615.9,481.9
VCC5V on VCC (split plane): 5486.92,-356.76 5486.92,-1698 5487.23,-1700.35 5487.92,-1702.02 5487.92,-1864 5487.92,-2303.24 5220.58,-2570.58 5219.14,-2572.46 5218.23,-2574.65 5217.92,-2577 5217.92,-2909.24 5097.24,-3029.92 4766,-3029.92 4763.65,-3030.23 4761.46,-3031.14 4759.58,-3032.58 4708.24,-3083.92 3039.76,-3083.92 3015.08,-3059.24 3015.08,-2896.76 3034.76,-2877.08 4569,-2877.08 4571.35,-2876.77 4573.54,-2875.86 4575.42,-2874.42 5167.42,-2282.42 5168.86,-2280.54 5169.13,-2279.9 5169.77,-2278.35 5170.08,-2276 5170.08,-383 5169.77,-380.65 5168.86,-378.46 5167.42,-376.58 5037.42,-246.58 5035.54,-245.14 5033.35,-244.23 5031,-243.92 3401,-243.92 3398.65,-244.23 3396.46,-245.14 3394.58,-246.58 3324.58,-316.58 3323.14,-318.46 3322.23,-320.65 3321.92,-323 3321.92,-614.24 3207.24,-728.92 2051,-728.92 2048.65,-729.23 2048.01,-729.5 2046.46,-730.14 2044.58,-731.58 2024.58,-751.58 2023.14,-753.46 2022.23,-755.65 2021.92,-758 2021.92,-1004.24 2007.24,-1018.92 1914.76,-1018.92 1900.08,-1004.24 1900.08,-686.76 1989.76,-597.08 3061,-597.08 3063.35,-596.77 3065.54,-595.86 3067.42,-594.42 3142.42,-519.42 3143.86,-517.54 3144.13,-516.9 3144.77,-515.35 3145.08,-513 3145.08,-383 3145.08,-196.76 3234.76,-107.08 5237.24,-107.08
VIN on VCC (split plane): 2579.58,-3139.42 2581.46,-3140.86 2582.56,-3141.32 2583.65,-3141.77 2586,-3142.08 5291,-3142.08 5293.35,-3141.77 5295.54,-3140.86 5297.42,-3139.42 5422.62,-3014.22 5684.38,-3014.22 5731.92,-3061.76 5731.92,-3259.24 5689.58,-3301.58 5555.24,-3435.92 3019.76,-3435.92 2988.42,-3404.58 2986.54,-3403.14 2984.35,-3402.23 2982,-3401.92 602,-3401.92 599.65,-3402.23 597.46,-3403.14 595.58,-3404.58 558.24,-3441.92 420.76,-3441.92 380.08,-3401.24 380.08,-3023.69 431.69,-2972.08 2412.24,-2972.08
VCC3V3 on VCC (split plane): 7615.9,-5027.9 -293.9,-5027.9 -293.9,481.9 7615.9,481.9

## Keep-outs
Keep-Out Layer:
  lines w8: -139,-4208 ccw(c-69,-4208) -69,-4278 6111,-4278 ccw(c6108.5,-4200.5) 6186,-4198 6186,67 ccw(c6116,67) 6116,137 -74,137 ccw(c-74,72) -139,72 -139,-4208

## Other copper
Top Layer:
  rectangle net GND: 5840,-1965 5870,-1910
  rectangle net EARTH: 3319,-479 3412,-168
  rectangle net EARTH: 3923,-453 3996,-163
  rectangle net EARTH: 1747,-4190 2554,-3818
  rectangle net NetC4_1: 4758,-1826 5021,-1762
  rectangle net NetC4_1: 4834,-1882 5021,-1820
  rectangle net +12V: 4579,-1930 4665,-1900
  rectangle net VCC3V3: 4791,-1622 4987,-1573
  rectangle net VCC3V3: 4669,-1659 5036,-1600
  rectangle net NetL11_2: 5160,-1594 5226,-1569
  rectangle net NetL11_2: 5132,-1610 5176,-1547
  rectangle net VCC5V: 5195,-1772 5338,-1697
  rectangle net VCC5V: 5190,-1772 5267,-1605
  rectangle net EARTH: 616,-4208 2571,-4048
  rectangle net EARTH: -49,-4258 2536,-4163
  rectangle net EARTH: 3841,-4208 3961,-3813
  rectangle net EARTH: 5491,-3918 5831,-3658
  rectangle net GND: 5046,-953 5091,-728
  rectangle net GND: 4876,-758 5091,-683
  rectangle net GND: 4806,-918 4896,-461
  rectangle net GND: 3111,-3408 3216,-3338
  rectangle net GND: 3141,-3408 3226,-3283
  rectangle net GND: 3141,-3293 3301,-3193
  rectangle net GND: 2966,-3513 3136,-3338
  rectangle net GND: 2086,-3253 2186,-3193
  rectangle net GND: 1886,-3303 2091,-3163
  rectangle net GND: 2266,-3393 2346,-3348
  rectangle net GND: 2206,-3393 2281,-3293
  rectangle net GND: 2311,-3478 2351,-3328
  rectangle net GND: 2196,-3508 2421,-3458
  rectangle net GND: 2621,-3593 2681,-3523
  rectangle net GND: 2581,-3553 2716,-3518
  rectangle net AUGND: 1701,-2953 1766,-2873
  rectangle net GND: 541,-4003 663,-3762.57
  rectangle net GND: 140,-3158 196,-3083
  rectangle net GND: 141,-3203 286,-3138
  rectangle net GND: 271,-3263 493.4,-3138
  rectangle net GND: 1711,-2088 1825.53,-2048
  rectangle net GND: 1711,-1768 1896,-1718
  rectangle net GND: 591,-2188 636,-2153
  rectangle net GND: 1021,-2208 1071,-2093
  rectangle net GND: 892,-2208 948,-1920
  rectangle net VCC3V3: 1081,-2208 1136,-2093
  rectangle net VCC3V3: 921,-1631 1076,-1583
  rectangle net VCC3V3: 331,-1898 396,-1758
  rectangle net VCC3V3: 331,-1763 446,-1643
  rectangle net VCC3V3: 1296,-1873 1361,-1833
  rectangle net VCC3V3: 2676,-1333 2786,-1163
  rectangle net VCC5V: 3171,-373 3301,-313
  rectangle net NetC52_1: 2971,-423 3126,-283
  rectangle net NetC52_1: 3036,-293 3241,-173
  rectangle net NetC52_1: 2981,-303 3056,-168
  rectangle net VCC3V3: 3175,-98 3251,2
  rectangle net VBUS: 3316,-3503 3486,-3448
  rectangle net AUGND: 1634,-3739 1702,-3580
  rectangle net AUGND: 1603,-3592 1701,-3476
  rectangle net AUGND: 1072,-3746 1224,-3584
  rectangle net AUGND: 1015,-3600 1246,-3480
  rectangle net AUGND: 950,-2654 1008,-2581
  rectangle net AUGND: 950,-2671 1009,-2627
  rectangle net AUGND: 1677,-2493 1781,-2360
  rectangle net VCC5V: 1896,-1033 2011,-658
  rectangle net VIN: 641,-3133 781,-2953
  rectangle net VIN: 1486,-3098 1606,-2928
  rectangle net VCC5V: 3051,-3148 3246,-2988
  rectangle net VIN: 276,-3433 496,-3283
  rectangle net VIN: 191,-3493 506,-3368
  rectangle net VIN: 191,-3733 246,-3433
  rectangle net NetP5_5: 262,-4147 303,-4119
  rectangle net NetC60_2: 421,-4015.4 515,-3643
  rectangle net EARTH: 2811,-3798 2851,-3738
  rectangle net EARTH: 3371,-4258 4871,-4098
  rectangle net +12V: 4786,-2348 4891,-2288
  rectangle net VBUS: 3281,-3508 3321,-3423
  rectangle net VBUS: 1881,-3518 2031,-3433
  rectangle net VIN: 5594,-2741 5940,-2622
  rectangle net VCC5V: 5291,-2013 5436,-1697
  rectangle net VCC5V: 5124,-2071 5440,-1958
  rectangle net +12V: 4764,-2451 5286,-2311
  rectangle net NetD2_K: 5121,-2644 5435,-2523
  rectangle net VIN: 5327,-2469 5572,-2317
  rectangle net NetD11_A: 276,-3703 341,-3573
  rectangle net VIN: 631,-2978 986,-2903
  rectangle net VIN: 1286,-2976 1610,-2903
  rectangle net NetR45_2: 1261,-2663 1286,-2638
  region net VIN: 5761,-2798 5691,-2798 5691,-2988 5761,-2988
  rectangle net VIN: 5641.99,-2418 5731,-2360.01
  rectangle net VIN: 5591,-2406.94 5751,-2298
  rectangle net VIN: 5561,-3278 5831,-3118
  rectangle net VIN: 5521,-2788 5701,-2638
  rectangle net VIN: 5686,-2818 5781,-2688
  rectangle net GVDD: 1156,-2663 1186,-2623
  rectangle net GVDD: 1161,-2658 1186,-2558
  rectangle net VBUS: 3229,-3506 3308,-3466
  rectangle net GND: 226,-2883 296,-2788
  rectangle net AUGND: 216,-2973 551,-2908
  rectangle net AUGND: 565.02,-3592.06 661,-3488
  rectangle net AUGND: 601,-3743 656,-3578
  rectangle net GND: 4761,-1233 4856,-1098
  rectangle net USB_OTG_VBUS: 4636,-392 4781,-339
  rectangle net EARTH: 3180,-480 3320,-400
  rectangle net GND: 3180,-565 3410,-495
  rectangle net GND: 3405,-561 3473,-525
  rectangle net GND: 4491,-278 4542,-253
  rectangle net GND: 4479,-301 4518,-253
  rectangle net GND: 4638,-476 4897,-405
  rectangle net GND: 5050,-2100 5100,-2000
  rectangle net GND: 4853,-2708 4940,-2664
  rectangle net GND: 5534,-3397 5820,-3341
  rectangle net GND: 5637,-3474 5701,-3361
  rectangle net GND: 5359,-3011 5412,-2884
  rectangle net GND: 5312,-2921 5453,-2872
  rectangle net GND: 5339,-2233 5463,-2169
  rectangle net GND: 5089,-2184 5199,-2137
  rectangle net GND: 5124,-2217 5166,-2100
  rectangle net GND: 5750,-2220 5785,-2110
  rectangle net GND: 5685,-2180 5985,-2155
  rectangle net GND: 5935,-2225 5965,-2110
  rectangle net GND: 5865,-2395 5995,-2320
  rectangle net GND: 5930,-2590 5970,-2475
  rectangle net GND: 5750,-2590 5785,-2485
  rectangle net GND: 5945,-1590 6015,-1535
Bottom Layer:
  rectangle net EARTH: 4680,-4260 5760,-3940
  rectangle net GND: 4639,-2080 4919,-1846
  rectangle net AUGND: 938,-2947 1323,-2691
  rectangle net GND: -53,-3689 359,-3215
  rectangle net NetP5_6: 64,-3763 91,-3728
  rectangle net NetP5_5: 27,-3763 57,-3728
GND (plane layer: these items are gaps in the copper):
  lines w18: 216,-3738 256,-3778 1681,-3778 1836,-3623 1836,-2395.2 1768.8,-2328 661,-2328 616,-2373 616,-2843 576,-2883 236,-2883 216,-2903 216,-3738
VCC (plane layer: these items are gaps in the copper):
  lines w18: 4711,-3093 3036,-3093 3006,-3063 3006,-2893 3031,-2868 4569,-2868 5161,-2276 5161,-383 5031,-253 3401,-253 3331,-323 3331,-618 3211,-738 2051,-738 2031,-758 2031,-1008 2011,-1028 1911,-1028 1891,-1008 1891,-683 1986,-588 3061,-588 3136,-513 3136,-383 3136,-193 3231,-98 5241,-98 5496,-353 5496,-1698 ; 4712,-3093 4766,-3039 5101,-3039 5227,-2913 5227,-2577 5497,-2307 5497,-1864 5497,-1689 5496,-1688 ; 371,-3405 417,-3451 562,-3451 602,-3411 2982,-3411 3016,-3445 5559,-3445 5696,-3308 5741,-3263 5741,-3058 5688.14,-3005.14 5418.86,-3005.14 5291,-3133 2586,-3133 2416,-2963 427.93,-2963 371,-3019.93 371,-3405

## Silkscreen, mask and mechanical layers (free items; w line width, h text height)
Top Overlay:
  lines w5: 5400,-1370 5400,-1355 5525,-1355 5525,-1675 5400,-1675 5400,-1365 ; 4505,-465 4505,-320 5050,-320 5050,-465 4505,-465 ; 5000,-3025 5055,-3025 5055,-3070 5170,-3070 5170,-2925 5175,-2920 5285,-2920 5290,-2915 5290,-2665 5155,-2665 5150,-2670 5150,-2725 5090,-2725 5090,-2860 5055,-2860 5055,-2910 5000,-2910 5000,-3025
  lines w10: 4441.31,-593.87 1803.52,-593.87 ccw(c1803.52,-731.66) 1665.72,-731.66 1665.72,-2582.06 ccw(c1803.52,-2582.06) 1803.52,-2719.85 4441.31,-2719.85 ccw(c4441.31,-2582.06) 4579.11,-2582.06 4579.11,-731.66 ; 4441.52,-593.87 cw(c4441.52,-731.66) 4579.31,-731.66
  text "OTG" at 4350,-145 h60 r90
  text "DEBUG" at 5616,-269 h60
  text "LVDS" at 1785,-290 h60 r90
  text "RED" at 2940,-370 h60 r180
  text "TX" at 5215,-395 h60
  text "RX" at 5300,-395 h60
  text "G" at 5390,-395 h60
  text "COM0" at 5580,-585 h60 r90
  text "MINI-PCIE" at 516,-883 h60
  text "1" at 1855,-920 h78.74
  text "RST" at 4660,-1020 h60 r90
  text "BAT" at 2892,-1636 h60 r90
  text "3.3V" at 4595,-1705 h60
  text "SIM" at 2530,-1800 h60 r270
  text "+5V" at 5640,-1830 h60 r90
  text "DC-IN" at 5807,-2119 h60
  text "B" at 5450,-2600 h60 r270
  text "+" at 5575,-2600 h60 r270
  text "1" at 1765,-2645 h78.74
  text "A" at 5580,-2990 h60 r270
  text "KEY" at 5331,-3048 h60
  text "+12V" at 5526,-3268 h60 r90
  text "ETH0" at 4021,-3398 h60
  text "GND" at 5526,-3413 h60 r90
  text "DC-IN" at 5862,-3614 h60
  text "COM1" at 5542,-3640 h60
  text "B-LIGHT" at 71,-4023 h40
  text "L-SPK" at 1121,-4028 h40 r90
  text "R-SPK" at 1691,-4028 h40 r90
Bottom Overlay:
  text "RMXX Smart cabinet V1.2" at 135,-345 h250 r90
Top Solder:
  rectangle: 1480,-1305 1650,-645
